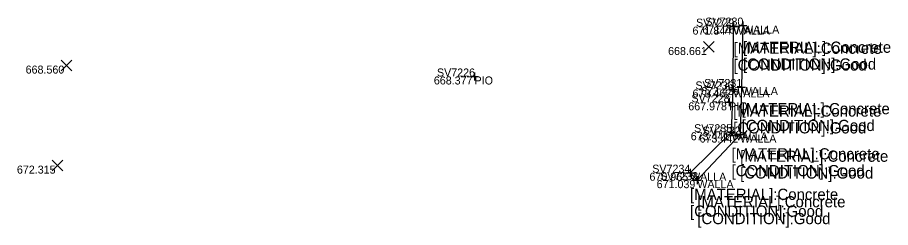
# Model space of a CAD drawing. Extents: x 1660019 to 1662995, y 619975 to 620342.
# Drawn here: x 1661131.5 to 1661240.7, y 620141.2 to 620167.4 of the extents above; entities that cross this region are included whole.
import ezdxf

# ---------------------------------------------------------------- set-up
doc = ezdxf.new("R2010")
doc.units = 0
for name, color, linetype in [('BR_X_Rail_Object', 7, 'Continuous'), ('BR_X_SV_Abut', 7, 'Continuous'), ('BR_X_SV_Abut_Text', 7, 'Continuous'), ('DR_X_Elev_Flow', 7, 'Continuous'), ('RD_P_GR_Lt', 7, 'Continuous'), ('RD_P_GR_Rt', 7, 'Continuous'), ('RD_X_GR_Bar', 7, 'Continuous'), ('RD_X_Wall', 7, 'Continuous'), ('SV_X_Text', 7, 'Continuous')]:
    doc.layers.add(name, color=color, linetype=linetype)

msp = doc.modelspace()

# ---------------------------------------------------------------- linework, layer by layer
at = {"layer": 'BR_X_SV_Abut'}
msp.add_lwpolyline([(1661221.02, 620166.27), (1661222.21, 620166.4), (1661222.04, 620158.72), (1661221.85, 620152.78), (1661216.5, 620147.08), (1661215.59, 620148.01), (1661220.77, 620153.07), (1661220.98, 620158.42)], close=True, dxfattribs=at)
at = {"layer": 'DR_X_Elev_Flow'}
for p, q in [((1661188.16, 620160.04), (1661189.16, 620160.04)), ((1661188.66, 620160.54), (1661188.66, 620159.54)), ((1661188.66, 620160.04), (1661188.66, 620160.04)), ((1661219.97, 620156.81), (1661220.97, 620156.81)), ((1661220.47, 620157.31), (1661220.47, 620156.31)), ((1661220.47, 620156.81), (1661220.47, 620156.81))]:
    msp.add_line(p, q, dxfattribs=at)
at = {"layer": 'RD_P_GR_Lt'}
for p, q in [((1661220.52, 620166.27), (1661221.52, 620166.27)), ((1661221.02, 620166.77), (1661221.02, 620165.77)), ((1661221.02, 620166.27), (1661221.02, 620166.27)), ((1661221.71, 620166.4), (1661222.71, 620166.4)), ((1661222.21, 620166.9), (1661222.21, 620165.9)), ((1661222.21, 620166.4), (1661222.21, 620166.4)), ((1661220.98, 620158.92), (1661220.98, 620157.92)), ((1661221.54, 620158.72), (1661222.54, 620158.72)), ((1661222.04, 620159.22), (1661222.04, 620158.22)), ((1661222.04, 620158.72), (1661222.04, 620158.72)), ((1661220.48, 620158.42), (1661221.48, 620158.42)), ((1661220.98, 620158.42), (1661220.98, 620158.42)), ((1661220.77, 620153.57), (1661220.77, 620152.57)), ((1661221.85, 620153.28), (1661221.85, 620152.28)), ((1661220.27, 620153.07), (1661221.27, 620153.07)), ((1661220.77, 620153.07), (1661220.77, 620153.07)), ((1661221.35, 620152.78), (1661222.35, 620152.78)), ((1661221.85, 620152.78), (1661221.85, 620152.78)), ((1661215.09, 620148.01), (1661216.09, 620148.01)), ((1661215.59, 620148.51), (1661215.59, 620147.51)), ((1661215.59, 620148.01), (1661215.59, 620148.01)), ((1661216, 620147.08), (1661217, 620147.08)), ((1661216.5, 620147.58), (1661216.5, 620146.58)), ((1661216.5, 620147.08), (1661216.5, 620147.08))]:
    msp.add_line(p, q, dxfattribs=at)
at = {"layer": 'RD_P_GR_Rt'}
for p, q in [((1661217.27, 620163.06), (1661218.6, 620164.39)), ((1661217.27, 620164.39), (1661218.6, 620163.06)), ((1661137, 620160.73), (1661138.33, 620162.07)), ((1661137, 620162.07), (1661138.33, 620160.73)), ((1661135.87, 620148.23), (1661137.2, 620149.56)), ((1661135.87, 620149.56), (1661137.2, 620148.23))]:
    msp.add_line(p, q, dxfattribs=at)

# ---------------------------------------------------------------- texts
at = {"layer": 'BR_X_Rail_Object'}
for p in [(1661188.66, 620159.04), (1661220.47, 620155.81)]:
    msp.add_text('PIO', height=1, dxfattribs=at).set_placement(p)
at = {"layer": 'BR_X_SV_Abut_Text'}
for s, p in [('SV7229', (1661216.34, 620166.27)), ('SV7230', (1661217.5, 620166.4)), ('671.844', (1661215.9, 620165.27)), ('671.767', (1661217.12, 620165.4)), ('WALLA', (1661221.02, 620165.27)), ('WALLA', (1661222.21, 620165.4)), ('SV7231', (1661217.36, 620158.72)), ('SV7236', (1661216.27, 620158.42)), ('673.439', (1661216.96, 620157.72)), ('WALLA', (1661222.04, 620157.72)), ('673.462', (1661215.9, 620157.42)), ('WALLA', (1661220.98, 620157.42)), ('SV7235', (1661216.1, 620153.07)), ('SV7232', (1661217.18, 620152.78)), ('673.441', (1661215.68, 620152.07)), ('673.442', (1661216.78, 620151.78)), ('WALLA', (1661220.77, 620152.07)), ('WALLA', (1661221.85, 620151.78)), ('SV7234', (1661210.87, 620148.01)), ('670.965', (1661210.52, 620147.01)), ('SV7233', (1661211.84, 620147.08)), ('WALLA', (1661215.59, 620147.01)), ('671.039', (1661211.42, 620146.08)), ('WALLA', (1661216.5, 620146.08))]:
    msp.add_text(s, height=1, dxfattribs=at).set_placement(p)
at = {"layer": 'RD_X_GR_Bar'}
for s, p in [('668.661', (1661212.85, 620162.72)), ('668.560', (1661132.55, 620160.4)), ('668.377', (1661183.57, 620159.04)), ('667.978', (1661215.37, 620155.81)), ('672.315', (1661131.46, 620147.9))]:
    msp.add_text(s, height=1, dxfattribs=at).set_placement(p)
at = {"layer": 'RD_X_Wall'}
for s, p in [('SV7226', (1661183.96, 620160.04)), ('SV7228', (1661215.77, 620156.81))]:
    msp.add_text(s, height=1, dxfattribs=at).set_placement(p)
at = {"layer": 'SV_X_Text'}
for s, p in [('[MATERIAL]:Concrete', (1661221.02, 620162.87)), ('[MATERIAL]:Concrete', (1661222.21, 620163)), ('[CONDITION]:Good', (1661221.02, 620160.77)), ('[CONDITION]:Good', (1661222.21, 620160.9)), ('[MATERIAL]:Concrete', (1661220.98, 620155.02)), ('[MATERIAL]:Concrete', (1661222.04, 620155.32)), ('[CONDITION]:Good', (1661220.98, 620152.92)), ('[CONDITION]:Good', (1661222.04, 620153.22)), ('[MATERIAL]:Concrete', (1661220.77, 620149.67)), ('[MATERIAL]:Concrete', (1661221.85, 620149.38)), ('[CONDITION]:Good', (1661220.77, 620147.57)), ('[CONDITION]:Good', (1661221.85, 620147.28)), ('[MATERIAL]:Concrete', (1661215.59, 620144.61)), ('[MATERIAL]:Concrete', (1661216.5, 620143.68)), ('[CONDITION]:Good', (1661215.59, 620142.51)), ('[CONDITION]:Good', (1661216.5, 620141.58))]:
    msp.add_text(s, height=1.4, dxfattribs=at).set_placement(p)

doc.saveas('drawing.dxf')
